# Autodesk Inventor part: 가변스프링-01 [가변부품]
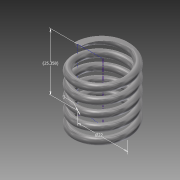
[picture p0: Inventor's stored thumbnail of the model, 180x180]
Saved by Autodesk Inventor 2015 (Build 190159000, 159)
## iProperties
Created: 2014-12
Part Number: 가변스프링-01 [가변부품]
Material: Steel, Carbon
Document SubType Name: Modeling
Designer: Deny
Density: 7.85 g/cm^3
Appearance: Semi-Polished
Mass: 18.694 g
Surface Area: 32.4187 cm^2
Volume: 2.3814 cm^3
Author: Deny
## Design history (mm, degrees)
sketch "Sketch1"
  geometry: L1 (0, 0)-(11, 0); L2 (11, 0)-(11, 25.358); L3 (11, 25.358)-(0, 25.358); L4 (0, 25.358)-(0, 0); C1 r 1.5 at (11, 0)
  constraints: 8 end point, 2 parallel, 1 centre point, 1 coincident, 1 horizontal, 1 perpendicular
  dimensions: "d0" = 3 diameter of C1; "d1" = 22 diameter of L2 L4; "d2" = 25.35829 distance between parallel lines of L1 L3 (derived)
coil "Coil1" sketch "Sketch1" pitch "d3" = 10; turns "d5" = 5; dims "d4" = 25.35829 (= d2), "d6" = 0, angle "d7" = 90 deg, angle "d8" = 90 deg, "d9" = 0, "d10" = 0
sketch "Sketch2"
  geometry: L1 (-12.5, 0)-(-9.5, 0) reference; 1 further point
  constraints: 1 horizontal alignment
extrude "Extrusion1" cut sketch "Sketch2" stored distance "d11" = 10; taper "d12" = 0 deg
workplane "Work Plane1"
sketch "Sketch3"
  geometry: L1 (1.5, 0)-(-1.5, 0) reference; 1 further point
  constraints: 1 horizontal alignment
extrude "Extrusion2" cut sketch "Sketch3" stored distance "d14" = 10; taper "d15" = 0 deg
body "Solid1"
node "Project Cut Edges1"
node "Project Cut Edges2"
other parameters: "d13" = 0
